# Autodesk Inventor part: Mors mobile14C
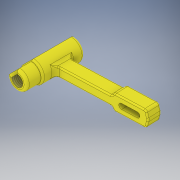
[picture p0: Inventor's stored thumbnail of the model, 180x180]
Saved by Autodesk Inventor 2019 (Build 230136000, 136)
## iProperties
Created: 2000-02
Part Number: Mors mobile14C
Material: Générique
Document SubType Name: Modeling
Designer: si-nd67
Density: 1 g/cm^3
Appearance: Jaune canari
Mass: 77.433 g
Surface Area: 266.449 cm^2
Volume: 77.433 cm^3
Sending System: SolidWorks 2014
Last Author: tjost
Last Saved: 2019-02-07
Author: si-nd67
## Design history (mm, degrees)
feature "Enlèv. mat.-Extru.6"
sketch "Esquisse1"
  geometry: 2 further points
  constraints: 1 coincident
hole "Perçage1" sketch "Esquisse1" at (0, 0) diameter "d0" = 17.294; stored, may be unused: countersink angle "d4" = 90 deg, drill point angle "d6" = 0 deg; dims "d1" = 40, "d2" = 4, "d3" = 2, "d5" = 40
sketch "Esquisse2"
  geometry: L1 (0, 0)-(-33.234, 0); L2 (0, 0)-(0, 17.862); L3 (0, 17.862)-(-32.422, 17.483); L4 (-32.422, 17.483)-(-33.234, 0)
  constraints: 8 end point, 1 horizontal, 1 vertical
extrude "Extrusion1" cut sketch "Esquisse2" extent not by distance; stored distance "d7" = 0; taper "d8" = 0 deg
node "Solide1"
